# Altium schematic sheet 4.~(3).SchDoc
size 420 x 297 mm
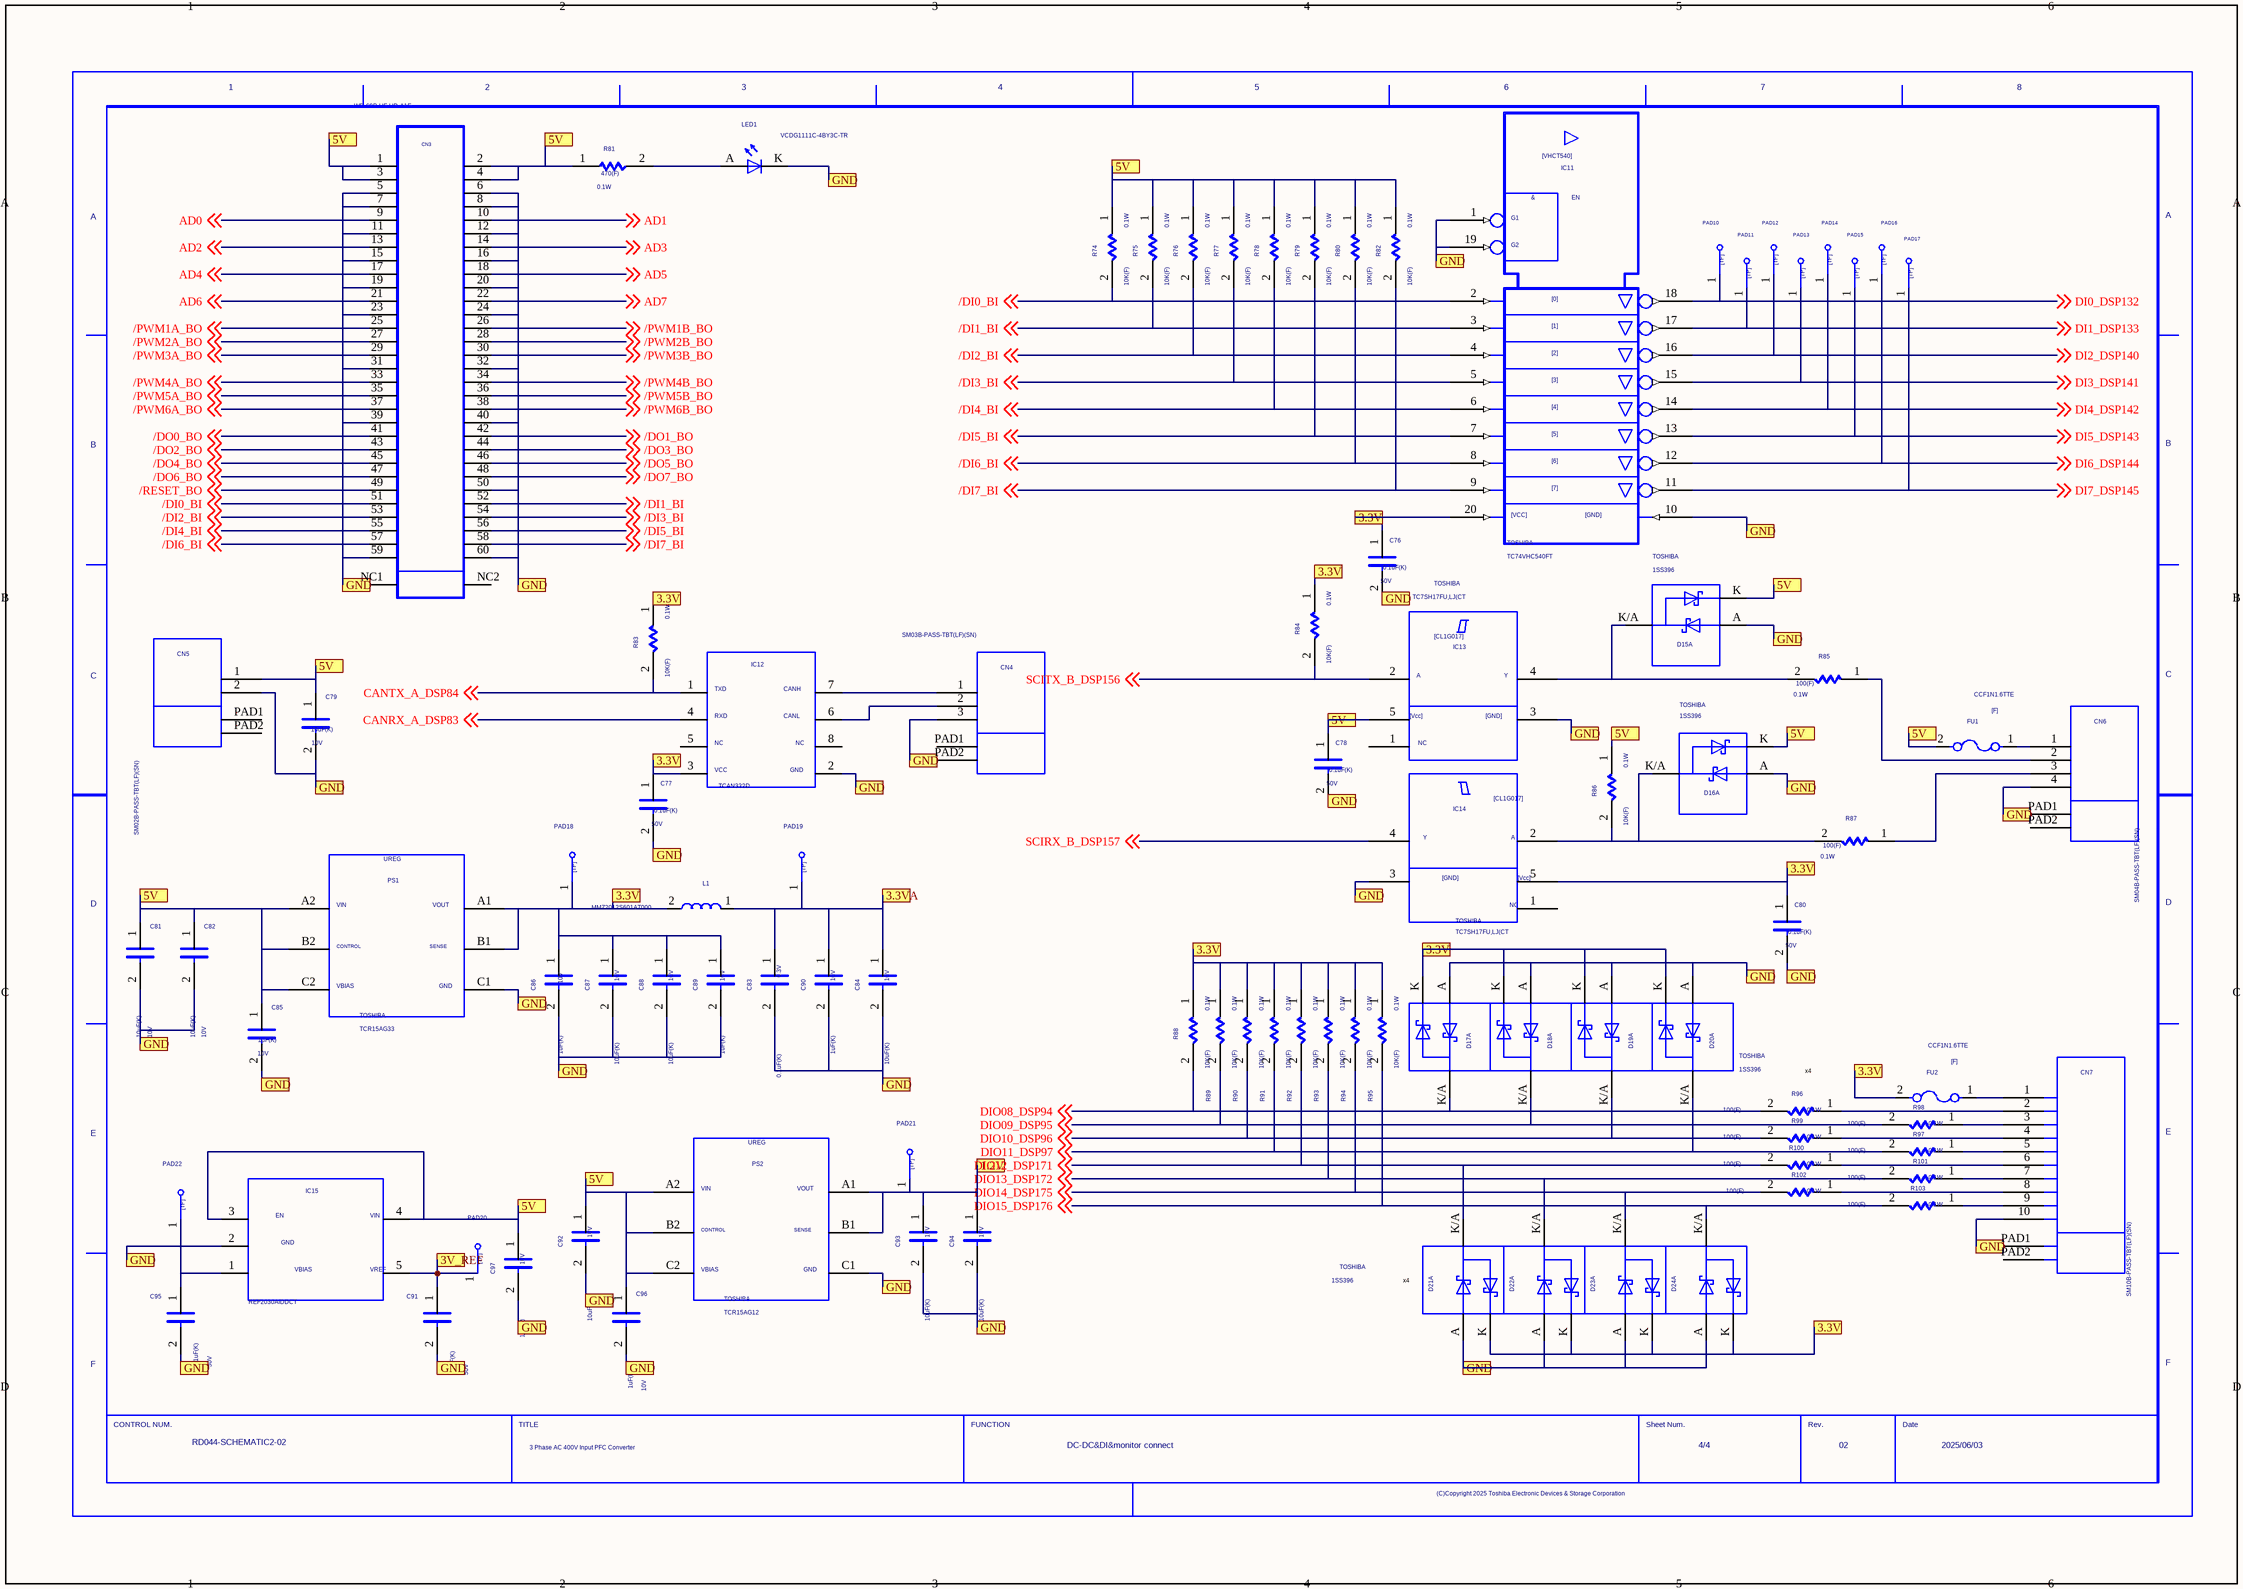
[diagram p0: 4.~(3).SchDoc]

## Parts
C76  VAL1: 0.1uF(K)  VAL2: 50V  (hidden comment: C)
C77  VAL1: 0.1uF(K)  VAL2: 50V  (hidden comment: C)
C78  VAL1: 0.1uF(K)  VAL2: 50V  (hidden comment: C)
C79  VAL1: 10uF(K)  VAL2: 10V  (hidden comment: C)
C80  VAL1: 0.1uF(K)  VAL2: 50V  (hidden comment: C)
C81  VAL1: 10uF(K)  VAL2: 10V  (hidden comment: C)
C82  VAL1: 10uF(K)  VAL2: 10V  (hidden comment: C)
C83  VAL1: 0.1uF(K)  VAL2: 6.3V  (hidden comment: C)
C84  VAL1: 10uF(K)  VAL2: 10V  (hidden comment: C)
C85  VAL1: 1uF(K)  VAL2: 10V  (hidden comment: C)
C86  VAL1: 1uF(K)  VAL2: 10V  (hidden comment: C)
C87  VAL1: 10uF(K)  VAL2: 10V  (hidden comment: C)
C88  VAL1: 10uF(K)  VAL2: 10V  (hidden comment: C)
C89  VAL1: 1uF(K)  VAL2: 10V  (hidden comment: C)
C90  VAL1: 1uF(K)  VAL2: 10V  (hidden comment: C)
C91  VAL1: 0.1uF(K)  VAL2: 50V  (hidden comment: C)
C92  VAL1: 10uF(K)  VAL2: 10V  (hidden comment: C)
C93  VAL1: 10uF(K)  VAL2: 10V  (hidden comment: C)
C94  VAL1: 10uF(K)  VAL2: 10V  (hidden comment: C)
C95  VAL1: 0.1uF(K)  VAL2: 50V  (hidden comment: C)
C96  VAL1: 1uF(K)  VAL2: 10V  (hidden comment: C)
C97  VAL1: 1uF(K)  VAL2: 10V  (hidden comment: C)
CN3  VAL3: WR-60P-HF-HD-A1E  (hidden comment: WR-60P)
CN4  VAL3: SM03B-PASS-TBT(LF)(SN)  (hidden comment: BM03B-PASS)
CN5  VAL3: SM02B-PASS-TBT(LF)(SN)  (hidden comment: BM02B-PASS)
CN6  VAL3: SM04B-PASS-TBT(LF)(SN)  (hidden comment: BM04B-PASS)
CN7  VAL3: SM10B-PASS-TBT(LF)(SN)  (hidden comment: SM10B-PASS)
D15  USERCOMPTEXT3: TOSHIBA  (hidden comment: 1SS396)  (part A of 3)
D16  USERCOMPTEXT3: TOSHIBA  (hidden comment: 1SS396)  (part A of 3)
D17  1SS396  (value not drawn)  (part A of 3)
D18  1SS396  (value not drawn)  (part A of 3)
D19  1SS396  (value not drawn)  (part A of 3)
D20  USERCOMPTEXT3: TOSHIBA  (hidden comment: 1SS396)  (part A of 3)
D21  USERCOMPTEXT3: TOSHIBA  (hidden comment: 1SS396)  (part A of 3)
D22  1SS396  (value not drawn)  (part A of 3)
D23  1SS396  (value not drawn)  (part A of 3)
D24  1SS396  (value not drawn)  (part A of 3)
FU1  VAL3: CCF1N1.6TTE  (hidden comment: F)
FU2  VAL3: CCF1N1.6TTE  (hidden comment: F)
IC11  USERCOMPTEXT3: TOSHIBA  VAL3: TC74VHC540FT  (hidden comment: VHC540)
IC12  TCAN332D
IC13  USERCOMPTEXT3: TOSHIBA  VAL3: TC7SH17FU,LJ(CT  (hidden comment: CL1G017)
IC14  USERCOMPTEXT3: TOSHIBA  VAL3: TC7SH17FU,LJ(CT  (hidden comment: CL1G017)
IC15  VAL3: REF2030AIDDCT  (hidden comment: REF)
L1  VAL3: MMZ2012S601AT000  (hidden comment: L)
LED1  VAL3: VCDG1111C-4BY3C-TR  (hidden comment: VCDG1111C)
PAD10  TP  (value not drawn)
PAD11  TP  (value not drawn)
PAD12  TP  (value not drawn)
PAD13  TP  (value not drawn)
PAD14  TP  (value not drawn)
PAD15  TP  (value not drawn)
PAD16  TP  (value not drawn)
PAD17  TP  (value not drawn)
PAD18  TP  (value not drawn)
PAD19  TP  (value not drawn)
PAD20  TP  (value not drawn)
PAD21  TP  (value not drawn)
PAD22  TP  (value not drawn)
PS1  USERCOMPTEXT3: TOSHIBA  VAL3: TCR15AG33  (hidden comment: L15AG)
PS2  USERCOMPTEXT3: TOSHIBA  VAL3: TCR15AG12  (hidden comment: L15AG)
R74  VAL2: 0.1W  VAL1: 10K(F)  (hidden comment: R)
R75  VAL2: 0.1W  VAL1: 10K(F)  (hidden comment: R)
R76  VAL2: 0.1W  VAL1: 10K(F)  (hidden comment: R)
R77  VAL2: 0.1W  VAL1: 10K(F)  (hidden comment: R)
R78  VAL2: 0.1W  VAL1: 10K(F)  (hidden comment: R)
R79  VAL2: 0.1W  VAL1: 10K(F)  (hidden comment: R)
R80  VAL2: 0.1W  VAL1: 10K(F)  (hidden comment: R)
R81  VAL2: 0.1W  VAL1: 470(F)  (hidden comment: R)
R82  VAL2: 0.1W  VAL1: 10K(F)  (hidden comment: R)
R83  VAL2: 0.1W  VAL1: 10K(F)  (hidden comment: R)
R84  VAL2: 0.1W  VAL1: 10K(F)  (hidden comment: R)
R85  VAL2: 0.1W  VAL1: 100(F)  (hidden comment: R)
R86  VAL2: 0.1W  VAL1: 10K(F)  (hidden comment: R)
R87  VAL2: 0.1W  VAL1: 100(F)  (hidden comment: R)
R88  VAL2: 0.1W  VAL1: 10K(F)  (hidden comment: R)
R89  VAL2: 0.1W  VAL1: 10K(F)  (hidden comment: R)
R90  VAL2: 0.1W  VAL1: 10K(F)  (hidden comment: R)
R91  VAL2: 0.1W  VAL1: 10K(F)  (hidden comment: R)
R92  VAL2: 0.1W  VAL1: 10K(F)  (hidden comment: R)
R93  VAL2: 0.1W  VAL1: 10K(F)  (hidden comment: R)
R94  VAL2: 0.1W  VAL1: 10K(F)  (hidden comment: R)
R95  VAL2: 0.1W  VAL1: 10K(F)  (hidden comment: R)
R96  VAL2: 0.1W  VAL1: 100(F)  (hidden comment: R)
R97  VAL2: 0.1W  VAL1: 100(F)  (hidden comment: R)
R98  VAL2: 0.1W  VAL1: 100(F)  (hidden comment: R)
R99  VAL2: 0.1W  VAL1: 100(F)  (hidden comment: R)
R100  VAL2: 0.1W  VAL1: 100(F)  (hidden comment: R)
R101  VAL2: 0.1W  VAL1: 100(F)  (hidden comment: R)
R102  VAL2: 0.1W  VAL1: 100(F)  (hidden comment: R)
R103  VAL2: 0.1W  VAL1: 100(F)  (hidden comment: R)
U?  DATE: 2025/06/03  DRAWINGNUMBER: RD044-SCHEMATIC2-02  TITLE: 3 Phase AC 400V Input PFC Converter  FUNCTION: DC-DC&DI&monitor connect  SHEETNUMBER: 4/4  REVISION: 02  (hidden comment: WAKU_DEF100_2018)

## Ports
1.2V, 3.3V, 3.3VA, 3V_REF, 5V, GND

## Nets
1.2V: C93.1 C94.1 PAD21.1 PS2.A1 PS2.B1 ; port 1.2V
3.3V: C76.1 C77.1 C80.1 C86.1 C87.1 C88.1 C89.1 D17.K D18.K D19.K D20.K D21.K D22.K D23.K D24.K FU2.2 IC11.20 IC12.3 IC14.5 L1.2 PAD18.1 PS1.A1 PS1.B1 R83.1 R84.1 R88.1 R89.1 R90.1 R91.1 R92.1 R93.1 R94.1 R95.1 ; port 3.3V
3.3VA: C83.1 C84.1 C90.1 L1.1 PAD19.1 ; port 3.3VA
3V_REF: C91.1 IC15.5 PAD20.1 ; port 3V_REF
5V: C78.1 C79.1 C81.1 C82.1 C85.1 C92.1 C96.1 C97.1 CN3.1 CN3.2 CN3.3 CN3.4 CN5.1 D15.K D16.K FU1.2 IC13.5 IC15.3 IC15.4 PS1.A2 PS1.B2 PS1.C2 PS2.A2 PS2.B2 PS2.C2 R74.1 R75.1 R76.1 R77.1 R78.1 R79.1 R80.1 R81.1 R82.1 R86.1 ; port 5V
/DI0_BI: CN3.51 IC11.2 R74.2 ; off-sheet /DI0_BI
/DI1_BI: CN3.52 IC11.3 R75.2 ; off-sheet /DI1_BI
/DI2_BI: CN3.53 IC11.4 R76.2 ; off-sheet /DI2_BI
/DI3_BI: CN3.54 IC11.5 R77.2 ; off-sheet /DI3_BI
/DI4_BI: CN3.55 IC11.6 R78.2 ; off-sheet /DI4_BI
/DI5_BI: CN3.56 IC11.7 R79.2 ; off-sheet /DI5_BI
/DI6_BI: CN3.57 IC11.8 R80.2 ; off-sheet /DI6_BI
/DI7_BI: CN3.58 IC11.9 R82.2 ; off-sheet /DI7_BI
/DO0_BO: CN3.41 ; off-sheet /DO0_BO
/DO1_BO: CN3.42 ; off-sheet /DO1_BO
/DO2_BO: CN3.43 ; off-sheet /DO2_BO
/DO3_BO: CN3.44 ; off-sheet /DO3_BO
/DO4_BO: CN3.45 ; off-sheet /DO4_BO
/DO5_BO: CN3.46 ; off-sheet /DO5_BO
/DO6_BO: CN3.47 ; off-sheet /DO6_BO
/DO7_BO: CN3.48 ; off-sheet /DO7_BO
/PWM1A_BO: CN3.25 ; off-sheet /PWM1A_BO
/PWM1B_BO: CN3.26 ; off-sheet /PWM1B_BO
/PWM2A_BO: CN3.27 ; off-sheet /PWM2A_BO
/PWM2B_BO: CN3.28 ; off-sheet /PWM2B_BO
/PWM3A_BO: CN3.29 ; off-sheet /PWM3A_BO
/PWM3B_BO: CN3.30 ; off-sheet /PWM3B_BO
/PWM4A_BO: CN3.33 ; off-sheet /PWM4A_BO
/PWM4B_BO: CN3.34 ; off-sheet /PWM4B_BO
/PWM5A_BO: CN3.35 ; off-sheet /PWM5A_BO
/PWM5B_BO: CN3.36 ; off-sheet /PWM5B_BO
/PWM6A_BO: CN3.37 ; off-sheet /PWM6A_BO
/PWM6B_BO: CN3.38 ; off-sheet /PWM6B_BO
/RESET_BO: CN3.49 ; off-sheet /RESET_BO
AD0: CN3.9 ; off-sheet AD0
AD1: CN3.10 ; off-sheet AD1
AD2: CN3.13 ; off-sheet AD2
AD3: CN3.14 ; off-sheet AD3
AD4: CN3.17 ; off-sheet AD4
AD5: CN3.18 ; off-sheet AD5
AD6: CN3.21 ; off-sheet AD6
AD7: CN3.22 ; off-sheet AD7
CANRX_A_DSP83: IC12.4 ; off-sheet CANRX_A_DSP83
CANTX_A_DSP84: IC12.1 R83.2 ; off-sheet CANTX_A_DSP84
DI0_DSP132: IC11.18 PAD10.1 ; off-sheet DI0_DSP132
DI1_DSP133: IC11.17 PAD11.1 ; off-sheet DI1_DSP133
DI2_DSP140: IC11.16 PAD12.1 ; off-sheet DI2_DSP140
DI3_DSP141: IC11.15 PAD13.1 ; off-sheet DI3_DSP141
DI4_DSP142: IC11.14 PAD14.1 ; off-sheet DI4_DSP142
DI5_DSP143: IC11.13 PAD15.1 ; off-sheet DI5_DSP143
DI6_DSP144: IC11.12 PAD16.1 ; off-sheet DI6_DSP144
DI7_DSP145: IC11.11 PAD17.1 ; off-sheet DI7_DSP145
DIO08_DSP94: D17.K/A R88.2 R96.2 ; off-sheet DIO08_DSP94
DIO09_DSP95: D18.K/A R89.2 R98.2 ; off-sheet DIO09_DSP95
DIO10_DSP96: D19.K/A R90.2 R99.2 ; off-sheet DIO10_DSP96
DIO11_DSP97: D20.K/A R91.2 R97.2 ; off-sheet DIO11_DSP97
DIO12_DSP171: D21.K/A R92.2 R100.2 ; off-sheet DIO12_DSP171
DIO13_DSP172: D22.K/A R93.2 R101.2 ; off-sheet DIO13_DSP172
DIO14_DSP175: D23.K/A R94.2 R102.2 ; off-sheet DIO14_DSP175
DIO15_DSP176: D24.K/A R95.2 R103.2 ; off-sheet DIO15_DSP176
GND: C76.2 C77.2 C78.2 C79.2 C80.2 C81.2 C82.2 C83.2 C84.2 C85.2 C86.2 C87.2 C88.2 C89.2 C90.2 C91.2 C92.2 C93.2 C94.2 C95.2 C96.2 C97.2 CN3.5 CN3.6 CN3.7 CN3.8 CN3.11 CN3.12 CN3.15 CN3.16 CN3.19 CN3.20 CN3.23 CN3.24 CN3.31 CN3.32 CN3.39 CN3.40 CN3.50 CN3.59 CN3.60 CN3.NC1 CN4.3 CN4.PAD2 CN5.2 CN6.4 CN6.PAD1 CN7.10 CN7.PAD1 D15.A D16.A D17.A D18.A D19.A D20.A D21.A D22.A D23.A D24.A IC11.1 IC11.10 IC11.19 IC12.2 IC13.3 IC14.3 IC15.2 LED1.K PS1.C1 PS2.C1 ; port GND
N16642513: C95.1 IC15.1 PAD22.1
N16664780: D15.K/A IC13.4 R85.2
N16668564: D16.K/A IC14.2 R86.2 R87.2
N16668568: CN6.3 R87.1
N16669496: CN4.1 IC12.7
N16669500: CN4.2 IC12.6
N16671270: CN6.2 R85.1
N16690596: LED1.A R81.2
N16817849: CN7.9 R103.1
N16817854: CN7.8 R102.1
N16817859: CN7.7 R101.1
N16817864: CN7.6 R100.1
N16817869: CN7.5 R97.1
N16817874: CN7.4 R99.1
N16817879: CN7.3 R98.1
N16817884: CN7.2 R96.1
N16840741: CN7.1 FU2.1
N16841842: CN6.1 FU1.1
SCIRX_B_DSP157: IC14.4 ; off-sheet SCIRX_B_DSP157
SCITX_B_DSP156: IC13.2 R84.2 ; off-sheet SCITX_B_DSP156

Not connected (* = marked no-connect by the designer): CN3 NC2; CN4 PAD1; CN5 PAD1 PAD2; CN6 PAD2; CN7 PAD2; IC12 5 8; IC13 1; IC14 1

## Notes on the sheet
- (near R96) x4
- x4

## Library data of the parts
C76-C78 C80 C91 C95 = C: OriginalSymbolOrigin: (2540,7620); CDBNAME: C-GRM188R71H104KA93D; USERCOMPTEXT1: 1608
C79 C81 C82 C84 C87 C88 C92-C94 = C: OriginalSymbolOrigin: (2540,7620); CDBNAME: C-GRM188R61A106KE69D; USERCOMPTEXT1: 1608
C83 = C: OriginalSymbolOrigin: (2540,7620); CDBNAME: C-GRM155R70J104KA01D; USERCOMPTEXT1: 1005
C85 C86 C89 C90 C96 C97 = C: OriginalSymbolOrigin: (2540,7620); CDBNAME: C-GRM188R71A105KA61D; USERCOMPTEXT1: 1608
CN3 = WR-60P: SAVEAREA0: -67682,-998,88845,96631; SAVECOUNT: 3; TIME: 09:42:27; UPDATEUSER: cae; UPDATETIME: 10:25:54; OriginalSymbolOrigin: (5080,91440); CDBNAME: CN-WR-60P-HF-HD-A1E
CN4 = BM03B-PASS: SAVEAREA0: -16737,-296,39143,28727; SAVECOUNT: 24; TIME: 13:28:28; UPDATEUSER: cae; UPDATETIME: 09:56:18; OriginalSymbolOrigin: (2540,25400); CDBNAME: CN-SM03B-PASS-TBT_LF_SN
CN5 = BM02B-PASS: SAVEAREA0: -14164,-269,36638,26116; SAVECOUNT: 26; TIME: 13:28:28; UPDATEUSER: cae; UPDATETIME: 09:55:50; OriginalSymbolOrigin: (2540,22860); CDBNAME: CN-SM02B-PASS-TBT_LF_SN
CN6 = BM04B-PASS: SAVEAREA0: -19295,-323,41666,31339; SAVECOUNT: 22; TIME: 13:28:28; UPDATEUSER: cae; UPDATETIME: 09:56:44; OriginalSymbolOrigin: (2540,27940); CDBNAME: CN-SM04B-PASS-TBT_LF_SN
CN7 = SM10B-PASS: SAVEAREA0: -33411,-485,58033,47009; SAVECOUNT: 23; TIME: 13:28:28; UPDATEUSER: cae; UPDATETIME: 14:27:01; OriginalSymbolOrigin: (2540,43180); CDBNAME: CN-SM10B-PASS-TBT_LF_SN
D15 D16 D20 D21 = 1SS396: SAVECOUNT: 7; SAVEAREA0: -5465,-437,27678,21425; TIME: 18:51:12; UPDATEUSER: cae; UPDATETIME: 10:39:29; OriginalSymbolOrigin: (5080,17780); CDBNAME: D-1SS396_AK
D17-D19 D22-D24 = 1SS396: SAVECOUNT: 7; SAVEAREA0: -5465,-437,27678,21425; TIME: 18:51:12; UPDATEUSER: cae; UPDATETIME: 10:39:29; OriginalSymbolOrigin: (5080,17780); USERCOMPTEXT3: TOSHIBA; CDBNAME: D-1SS396_AK
FU1 FU2 = F: OriginalSymbolOrigin: (2540,5080); CDBNAME: FU-CCF1N1.6TTE
IC11 = VHC540: SAVEAREA0: -64373,-927,110287,89788; TIME: 09:37:32; UPDATEUSER: cae; SAVECOUNT: 1; OriginalSymbolOrigin: (7620,83820); CDBNAME: IC-TC74VHC540FT
IC12 = TCAN332D: SAVECOUNT: 26; SAVEAREA0: -15475,-323,45487,31339; TIME: 17:47:02; UPDATEUSER: cae; UPDATETIME: 14:38:54; OriginalSymbolOrigin: (5080,27940); CDBNAME: IC-TCAN332D
IC13 IC14 = CL1G017: TIME: 16:09:43; UPDATEUSER: tomizawa-y; UPDATETIME: 12:13:51; SAVECOUNT: 12; SAVEAREA0: -8892,-376,44463,33313; OriginalSymbolOrigin: (7620,30480); MAXGCOUNT: 1; CDBNAME: IC-TC7SH17F; ADSCNVFLAG: ON
IC15 = REF: SAVECOUNT: 25; SAVEAREA0: -10386,-296,45494,28727; TIME: 17:47:02; UPDATEUSER: cae; UPDATETIME: 11:05:59; OriginalSymbolOrigin: (5080,25400); CDBNAME: IC-REF2030AIDDCT
L1 = L: OriginalSymbolOrigin: (2540,5080); CDBNAME: L-MMZ2012S601AT000
LED1 = VCDG1111C: SAVEAREA0: -6769,-859,19276,16321; TIME: 14:49:55; UPDATEUSER: cae; UPDATETIME: 10:51:12; SAVECOUNT: 5; OriginalSymbolOrigin: (5080,7620); CDBNAME: LED-VCDG1111C-4BY3C-TR
PAD10 PAD18-PAD22 = TP: TIME: 16:12:21; UPDATEUSER: fukuda-y; UPDATETIME: 16:18:11; SAVECOUNT: 2; SAVEAREA0: -242,-92,12810,7836; OriginalSymbolOrigin: (0,7620); CDBNAME: TP-PAD1.0; VAL3: TP_PAD
PAD11-PAD17 = TP: TIME: 16:12:21; UPDATEUSER: fukuda-y; UPDATETIME: 16:18:11; SAVECOUNT: 2; SAVEAREA0: -242,-92,12810,7836; OriginalSymbolOrigin: (0,7620); CDBNAME: TP-PAD1.0
PS1 = L15AG: TIME: 08:44:39; UPDATEUSER: cae; UPDATETIME: 13:17:54; SAVECOUNT: 102; SAVEAREA0: -14581,-371,55282,35914; OriginalSymbolOrigin: (7620,33020); CDBNAME: PS-TCR15AG33
PS2 = L15AG: TIME: 08:44:39; UPDATEUSER: cae; UPDATETIME: 13:17:54; SAVECOUNT: 102; SAVEAREA0: -14581,-371,55282,35914; OriginalSymbolOrigin: (7620,33020); CDBNAME: PS-TCR15AG12
R74-R80 R82-R84 R86 R88-R95 = R: OriginalSymbolOrigin: (5080,5080); CDBNAME: R-ERJ3EKF1002V; USERCOMPTEXT1: 1608
R81 = R: OriginalSymbolOrigin: (5080,5080); CDBNAME: R-ERJ3EKF4700V; USERCOMPTEXT1: 1608
R85 R87 R96-R103 = R: OriginalSymbolOrigin: (5080,5080); CDBNAME: R-ERJ3EKF1000V; USERCOMPTEXT1: 1608
U? = WAKU_DEF100_2018: PLOTTIME: HH:MM; SAVEAREA0: -45080,-4508,463680,304612; TIME: 13:54:34; UPDATEUSER: e5025010; UPDATETIME: 16:01:41; SAVECOUNT: 4; OriginalSymbolOrigin: (10160,284480); SHTSAVECOUNT: 6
